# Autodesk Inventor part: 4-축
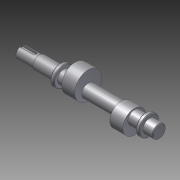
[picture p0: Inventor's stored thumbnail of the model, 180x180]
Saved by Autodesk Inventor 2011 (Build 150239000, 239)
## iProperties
Created: 2014-12
Part Number: 4-축
Document SubType Name: Modeling
Designer: user
Density: 1 g/cm^3
Author: user
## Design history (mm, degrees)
sketch "스케치2"
  geometry: L1 (90, 0)-(-90, 0); L2 (39, 8.5)-(39, 13); L3 (39, 13)-(34, 13); L4 (34, 13)-(34, 8.5); L5 (34, 8.5)-(-19.517, 8.5); L6 (-19.517, 8.5)-(-72, 8.5); L7 (-72, 8.5)-(-72, 13); L8 (-72, 13)-(-77, 13); L9 (-77, 13)-(-77, 8.5); L10 (-77, 8.5)-(-90, 8.5); L11 (-90, 8.5)-(-90, 0); L12 (90, 0)-(90, 7.5); L13 (90, 7.5)-(66, 7.5); L14 (66, 7.5)-(66, 8.5); L15 (66, 8.5)-(39, 8.5); 2 further points
  constraints: 30 end point, 4 perpendicular, 3 parallel, 2 collinear, 1 coincident, 1 horizontal, 1 midpoint
  dimensions: "d0" = 180 distance of L1.start L1.end; "d1" = 7.5 distance between parallel lines of L1 L13; "d2" = 8.5 distance between parallel lines of L1 L15; "d3" = 13 distance between parallel lines of L1 L3; "d4" = 8.5 distance between parallel lines of L1 L5; "d5" = 13 distance between parallel lines of L1 L8; "d6" = 8.5 distance between parallel lines of L1 L10; "d7" = 24 distance of L12.end L13.end; "d8" = 27 distance of L14.end L2.start; "d9" = 5 distance of L2.end L3.end; "d10" = 13 distance of L9.end L10.end; "d11" = 5 distance of L7.end L8.end
revolve "회전1" sketch "스케치2" stored, may be unused: angle "d12" = 90 deg
node "작업 평면1"
sketch "스케치3"
  geometry: C1 r 15 at (5, 0); 1 further point
  constraints: 1 centre point, 1 horizontal alignment
  dimensions: "d14" = 30 diameter of C1; "d15" = 5 distance of C1.centre point (0, 0)
extrude "돌출1" join sketch "스케치3" stored distance "d16" = 17; taper "d17" = 0 deg
node "작업 평면2"
sketch "스케치4"
  geometry: C1 r 17.5 at (6, 0); 1 further point
  constraints: 1 centre point
  dimensions: "d19" = 35 diameter of C1; "d20" = 6 distance of C1.centre point (0, 0)
extrude "돌출2" join sketch "스케치4" stored distance "d21" = 17; taper "d22" = 0 deg
sketch "스케치5"
  geometry: L1 (-90, -8.5)-(-90, 8.5) reference; L2 (-90, 8.5)-(-77, 8.5) reference; L3 (-77, 8.5)-(-77, 13) reference; L4 (-77, 13)-(-72, 13) reference; L5 (-72, 13)-(-72, 8.5) reference; L6 (-72, 8.5)-(-57.5, 8.5) reference; L7 (-57.5, 8.5)-(-57.5, 10) reference; L8 (-57.5, 10)-(-40.5, 10) reference; L9 (-40.5, 10)-(-40.5, 8.5) reference; L10 (-40.5, 8.5)-(2.5, 8.5) reference; L11 (2.5, 8.5)-(2.5, 23.5) reference; L12 (2.5, 23.5)-(19.5, 23.5) reference; L13 (19.5, 23.5)-(19.5, 8.5) reference; L14 (19.5, 8.5)-(34, 8.5) reference; L15 (34, 8.5)-(34, 13) reference; L16 (34, 13)-(39, 13) reference; L17 (39, 13)-(39, 8.5) reference; L18 (39, 8.5)-(66, 8.5) reference; L19 (66, 8.5)-(66, 7.5) reference; L20 (66, 7.5)-(90, 7.5) reference; L21 (90, 7.5)-(90, -7.5) reference; L22 (90, -7.5)-(66, -7.5) reference; L23 (66, -7.5)-(66, -8.5) reference; L24 (66, -8.5)-(39, -8.5) reference; L25 (39, -8.5)-(39, -13) reference; L26 (39, -13)-(34, -13) reference; L27 (34, -13)-(34, -8.5) reference; L28 (34, -8.5)-(19.5, -8.5) reference; L29 (19.5, -8.5)-(19.5, -11.5) reference; L30 (19.5, -11.5)-(2.5, -11.5) reference; L31 (2.5, -11.5)-(2.5, -8.5) reference; L32 (2.5, -8.5)-(-40.5, -8.5) reference; L33 (-40.5, -8.5)-(-40.5, -20) reference; L34 (-40.5, -20)-(-57.5, -20) reference; L35 (-57.5, -20)-(-57.5, -8.5) reference; L36 (-57.5, -8.5)-(-72, -8.5) reference; L37 (-72, -8.5)-(-72, -13) reference; L38 (-72, -13)-(-77, -13) reference; L39 (-77, -13)-(-77, -8.5) reference; L40 (-77, -8.5)-(-90, -8.5) reference; L41 (70, 7.5)-(70, 4.5); L42 (70, 4.5)-(90, 4.5); 1 further point
  constraints: 4 end point, 2 perpendicular, 2 point on line
  dimensions: "d23" = 3 distance of L41.start L41.end; "d24" = 20 distance between parallel lines of L21 L41
extrude "돌출3" cut sketch "스케치5" stored distance "d25" = 5; taper "d26" = 0 deg
fillet "모깎기1" dims "d27" = 2.5
chamfer "모따기1" distance "d28" = 1; stored, may be unused: second distance "d29" = 2, angle "d30" = 45 deg
chamfer "모따기2" distance "d31" = 1; stored, may be unused: second distance "d32" = 2, angle "d33" = 45 deg
node "솔리드1"
node "절단 모서리 투영1"
other parameters: "d13" = -41, "d18" = -79
